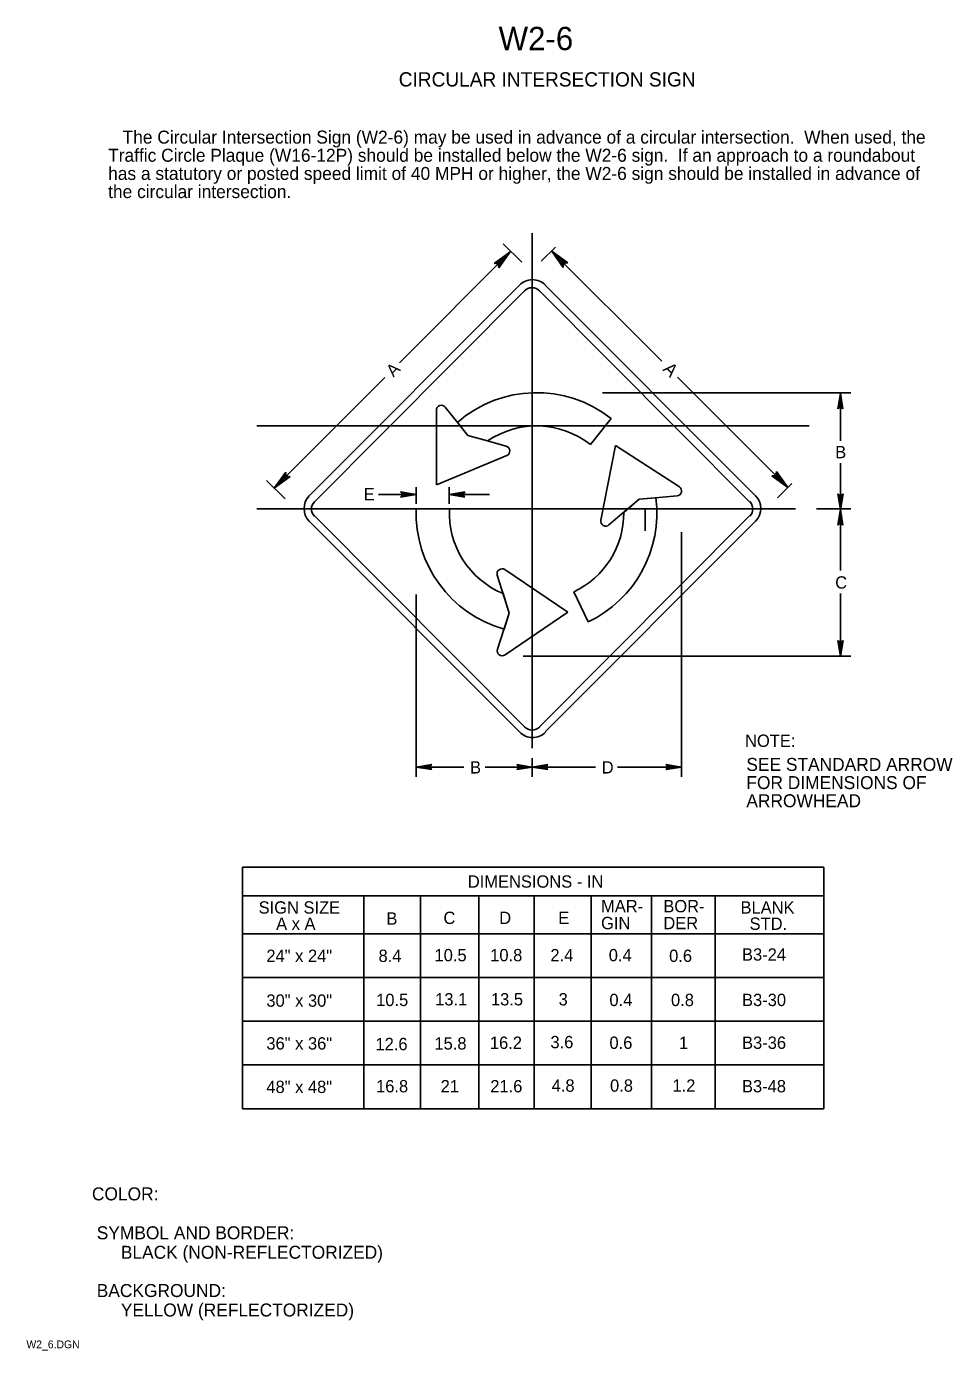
# Model space of a CAD drawing. Extents: x 0.013 to 0.191, y 0.004 to 0.259.
import ezdxf

# ---------------------------------------------------------------- set-up
doc = ezdxf.new("R2010")
doc.units = 0
for name, color, linetype in [('1', 7, 'Continuous'), ('2', 7, 'Continuous'), ('3', 7, 'Continuous')]:
    doc.layers.add(name, color=color, linetype=linetype)

# ---------------------------------------------------------------- blocks, each defined once
blk = doc.blocks.new('RARROW')
at = {"layer": '3'}
for p, q in [((-2.156, 0.28500000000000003), (-2.2665, 0.384625)), ((-2.2665, 0.384625), (0, 0)), ((0, 0), (-2.2665, -0.379125)), ((-2.156, 0.28500000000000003), (-2.075625, 0.12075)), ((0, 0), (-2.156, 0.28500000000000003)), ((-2.14975, -0.2705), (0, 0)), ((-2.075625, 0.12075), (0, 0)), ((0, 0), (-2.074, -0.108)), ((-2.2665, -0.379125), (-2.14975, -0.2705)), ((-2.074, -0.108), (-2.14975, -0.2705))]:
    blk.add_line(p, q, dxfattribs=at)

msp = doc.modelspace()

# ---------------------------------------------------------------- linework, layer by layer
at = {"layer": '2'}
for p, q in [((0.09568552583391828, 0.18279025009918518), (0.09769312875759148, 0.1802751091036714)), ((0.0957700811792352, 0.18268431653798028), (0.09769312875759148, 0.1802751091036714)), ((0.12133620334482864, 0.17850114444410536), (0.12529810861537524, 0.18352740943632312)), ((0.09769312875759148, 0.1802751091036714), (0.10149251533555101, 0.17920169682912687)), ((0.09769312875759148, 0.1802751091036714), (0.10081141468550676, 0.1793941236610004)), ((0.08775000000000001, 0.17030520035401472), (0.08775000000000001, 0.1671072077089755)), ((0.094125, 0.17030520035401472), (0.094125, 0.1671072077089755)), ((0.09415526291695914, 0.1661072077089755), (0.08775000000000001, 0.1661072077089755)), ((0.13074093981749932, 0.16800281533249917), (0.12773569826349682, 0.1654377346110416)), ((0.13394559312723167, 0.1682750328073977), (0.13074093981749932, 0.16800281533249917)), ((0.13381247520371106, 0.16826372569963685), (0.13074093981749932, 0.16800281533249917)), ((0.138875, 0.1616072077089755), (0.138875, 0.11448220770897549)), ((0.08775000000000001, 0.1496072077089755), (0.08775000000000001, 0.11448220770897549)), ((0.10447937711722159, 0.14979755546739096), (0.105681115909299, 0.14600468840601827)), ((0.105681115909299, 0.14600468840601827), (0.10470659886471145, 0.14909501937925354)), ((0.11813620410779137, 0.15012827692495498), (0.12087905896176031, 0.14434582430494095)), ((0.105681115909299, 0.14600468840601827), (0.10469034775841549, 0.14296376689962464)), ((0.10472218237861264, 0.1430750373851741), (0.105681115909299, 0.14600468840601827)), ((0.08775000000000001, 0.116375), (0.09693749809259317, 0.116375)), ((0.10106250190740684, 0.116375), (0.110125, 0.116375)), ((0.110125, 0.116375), (0.12231250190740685, 0.116375)), ((0.12656250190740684, 0.116375), (0.138875, 0.116375))]:
    msp.add_line(p, q, dxfattribs=at)
for radius, start, end in [(0.023200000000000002, 51.75337929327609, 131.0986026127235), (0.016800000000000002, 51.75338012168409, 124.20282927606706), (0.023200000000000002, 178.02389171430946, 254.38226787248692), (0.016800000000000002, 177.2705973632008, 247.39753928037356), (0.023200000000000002, 295.3769334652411, 7.349614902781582), (0.016800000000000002, 295.37693352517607, 0.4451615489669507)]:
    msp.add_arc((0.11093620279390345, 0.1653072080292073), radius, start, end, dxfattribs=at)
at = {"layer": '3'}
for p, q in [((0.10809834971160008, 0.21363385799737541), (0.1045232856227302, 0.21720892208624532)), ((0.110125, 0.2192322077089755), (0.110125, 0.1199822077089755)), ((0.08451462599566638, 0.19426462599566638), (0.10599110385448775, 0.21574110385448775)), ((0.1118516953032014, 0.21383413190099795), (0.11458199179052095, 0.21656442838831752)), ((0.1350682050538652, 0.19455679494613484), (0.11382128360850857, 0.21580371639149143)), ((0.067125, 0.168625), (0.107625, 0.20925)), ((0.112625, 0.20925), (0.153125, 0.168625)), ((0.068125, 0.1675), (0.108625, 0.208125)), ((0.1115, 0.208125), (0.152, 0.1675)), ((0.060375, 0.170125), (0.08166862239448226, 0.19141862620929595)), ((0.13809929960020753, 0.19152570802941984), (0.15937500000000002, 0.17025)), ((0.123625, 0.1885), (0.1715, 0.1885)), ((0.1695, 0.1792322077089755), (0.1695, 0.1884822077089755)), ((0.09168351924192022, 0.17072331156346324), (0.09163820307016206, 0.18511620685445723)), ((0.09334848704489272, 0.18571811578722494), (0.0957700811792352, 0.18268431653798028)), ((0.057, 0.182125), (0.1635, 0.182125)), ((0.0957700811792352, 0.18268431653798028), (0.09769312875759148, 0.1802751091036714)), ((0.09769312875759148, 0.1802751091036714), (0.10081141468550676, 0.1793941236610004)), ((0.10081141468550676, 0.1793941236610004), (0.10508310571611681, 0.17818727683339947)), ((0.10519276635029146, 0.1763778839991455), (0.09168351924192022, 0.17072331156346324)), ((0.1233345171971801, 0.16393122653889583), (0.12613620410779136, 0.1783056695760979)), ((0.12613620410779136, 0.1783056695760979), (0.13846514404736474, 0.17038604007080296)), ((0.1695, 0.1661072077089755), (0.1695, 0.1749175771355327)), ((0.0624779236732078, 0.16803030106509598), (0.05890296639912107, 0.17160525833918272)), ((0.15740165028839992, 0.16825885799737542), (0.16014460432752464, 0.17100181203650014)), ((0.0805, 0.168875), (0.08775000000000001, 0.168875)), ((0.094125, 0.168875), (0.10187845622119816, 0.168875)), ((0.13802755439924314, 0.16862176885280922), (0.13381247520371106, 0.16826372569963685)), ((0.057, 0.1661072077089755), (0.160875, 0.1661072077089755)), ((0.12827629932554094, 0.16589915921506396), (0.12490002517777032, 0.16301738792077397)), ((0.13074093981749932, 0.16800281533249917), (0.12827629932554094, 0.16589915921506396)), ((0.13381247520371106, 0.16826372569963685), (0.13074093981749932, 0.16800281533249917)), ((0.131875, 0.166125), (0.131875, 0.161875)), ((0.131875, 0.166125), (0.131875, 0.163625)), ((0.131875, 0.166125), (0.131875, 0.163625)), ((0.1715, 0.1661072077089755), (0.164875, 0.1661072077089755)), ((0.1695, 0.1542322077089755), (0.1695, 0.1661072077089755)), ((0.107625, 0.123125), (0.067125, 0.16375)), ((0.108625, 0.124125), (0.068125, 0.16475)), ((0.152, 0.16475), (0.1115, 0.124125)), ((0.153125, 0.16375), (0.112625, 0.123125)), ((0.10470659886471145, 0.14909501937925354), (0.10337162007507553, 0.15332841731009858)), ((0.10482412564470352, 0.1544129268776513), (0.11696407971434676, 0.14622173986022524)), ((0.105681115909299, 0.14600468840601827), (0.10470659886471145, 0.14909501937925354)), ((0.1695, 0.13775), (0.1695, 0.149832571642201)), ((0.10472218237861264, 0.1430750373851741), (0.105681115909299, 0.14600468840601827)), ((0.11696407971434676, 0.14622173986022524), (0.10485965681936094, 0.13796302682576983)), ((0.103406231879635, 0.13905466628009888), (0.10472218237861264, 0.1430750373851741)), ((0.110125, 0.14300000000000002), (0.110125, 0.144875)), ((0.108375, 0.13775), (0.1715, 0.13775)), ((0.110125, 0.1181072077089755), (0.110125, 0.11448220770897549)), ((0.054294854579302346, 0.09709144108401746), (0.16627504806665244, 0.09709144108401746)), ((0.054294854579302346, 0.09709144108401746), (0.054294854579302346, 0.05052360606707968)), ((0.16627504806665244, 0.09709144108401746), (0.16627504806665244, 0.05052360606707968)), ((0.16627504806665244, 0.09152782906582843), (0.054294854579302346, 0.09152782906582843)), ((0.07764135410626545, 0.09152782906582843), (0.07764135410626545, 0.05052360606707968)), ((0.08859135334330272, 0.09152782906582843), (0.08859135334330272, 0.05052360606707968)), ((0.09979911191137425, 0.09152782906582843), (0.09979911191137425, 0.05052360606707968)), ((0.11049135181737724, 0.09152782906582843), (0.11049135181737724, 0.05052360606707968)), ((0.1214552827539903, 0.09152782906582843), (0.1214552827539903, 0.05052360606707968)), ((0.13307547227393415, 0.09152782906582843), (0.13307547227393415, 0.05052360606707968)), ((0.1453588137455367, 0.09152782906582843), (0.1453588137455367, 0.05052360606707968)), ((0.054294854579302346, 0.08426226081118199), (0.16627504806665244, 0.08426226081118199)), ((0.054294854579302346, 0.07582759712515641), (0.16627504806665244, 0.07582759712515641)), ((0.054294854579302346, 0.06739293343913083), (0.16627504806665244, 0.06739293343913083)), ((0.054294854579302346, 0.05895826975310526), (0.16627504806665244, 0.05895826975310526)), ((0.054294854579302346, 0.05052360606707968), (0.16627504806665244, 0.05052360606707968))]:
    msp.add_line(p, q, dxfattribs=at)
for centre, radius, start, end in [((0.11014096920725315, 0.20674707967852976), 0.003536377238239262, 44.423908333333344, 135.3533277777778), ((0.11007125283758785, 0.20670173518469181), 0.0020166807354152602, 44.88986111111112, 135.81928055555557), ((0.09259819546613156, 0.18511922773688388), 0.00096, 38.59706823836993, 180.18039620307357), ((0.10482209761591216, 0.1772634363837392), 0.0009600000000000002, 292.7127526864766, 74.22383721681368), ((0.06959537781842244, 0.16616970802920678), 0.003470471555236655, 135.38381666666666, 224.61618055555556), ((0.13794630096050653, 0.16957832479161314), 0.0009600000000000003, 274.85525458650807, 57.28489031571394), ((0.1506301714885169, 0.16615999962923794), 0.003517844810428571, 316.1381361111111, 45.12422222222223), ((0.0695185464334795, 0.16610720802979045), 0.0019577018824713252, 135.38381666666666, 224.61618055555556), ((0.15060956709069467, 0.1661123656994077), 0.0019956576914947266, 315.85381666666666, 44.83990277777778), ((0.1242767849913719, 0.1637475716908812), 0.00096, 168.97089764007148, 310.4819776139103), ((0.10428717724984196, 0.15361713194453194), 0.00096, 55.99129694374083, 197.50237691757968), ((0.1043185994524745, 0.13875602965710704), 0.0009600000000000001, 161.87565389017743, 304.3052896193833), ((0.11018066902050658, 0.12552070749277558), 0.0034716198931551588, 223.19229722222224, 315.73071111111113), ((0.11010323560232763, 0.12550403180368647), 0.002011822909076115, 223.10040555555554, 315.63881944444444)]:
    msp.add_arc(centre, radius, start, end, dxfattribs=at)

# ---------------------------------------------------------------- block references
for p, xscale, yscale, rotation in [((0.105875, 0.215625), 0.0016545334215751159, 0.0016366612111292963, 44.999999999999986), ((0.113875, 0.21575), 0.0016545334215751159, 0.0016366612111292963, 135.00000000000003), ((0.1695, 0.18837500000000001), 0.0013236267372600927, 0.001309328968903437, 90), ((0.060375, 0.170125), 0.001654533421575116, 0.001636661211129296, -135), ((0.15937500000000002, 0.17025), 0.0016545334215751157, 0.001636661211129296, -45), ((0.094125, 0.168875), 0.0013236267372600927, 0.001309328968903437, 180), ((0.1695, 0.166), 0.0013236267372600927, 0.001309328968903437, -90), ((0.1695, 0.166), 0.0013236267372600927, 0.001309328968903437, 90), ((0.1695, 0.13775), 0.0013236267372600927, 0.001309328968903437, -90), ((0.08775000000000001, 0.116375), 0.0013236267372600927, 0.001309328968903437, 180), ((0.110125, 0.116375), 0.0013236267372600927, 0.001309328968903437, 180)]:
    msp.add_blockref('RARROW', p, dxfattribs=dict(at, xscale=xscale, yscale=yscale, rotation=rotation))
at = {"layer": '3', "xscale": 0.0013236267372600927, "yscale": 0.001309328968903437}
for p in [(0.08775000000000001, 0.168875), (0.110125, 0.116375), (0.138875, 0.116375)]:
    msp.add_blockref('RARROW', p, dxfattribs=at)

# ---------------------------------------------------------------- texts
at = {"layer": '1'}
for s, height, p in [('W2-6', 0.0045000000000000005, (0.10362500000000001, 0.2545)), ('CIRCULAR INTERSECTION SIGN', 0.00275025, (0.084375, 0.2475)), ('NOTE:', 0.0023752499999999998, (0.151125, 0.12025)), ('SEE STANDARD ARROW', 0.0024997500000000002, (0.151375, 0.115625)), ('FOR DIMENSIONS OF', 0.0024997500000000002, (0.151375, 0.112125)), ('ARROWHEAD', 0.0024997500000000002, (0.151375, 0.108625)), ('COLOR:', 0.0024997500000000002, (0.02525, 0.032875)), (' SYMBOL AND BORDER:', 0.0024997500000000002, (0.02525, 0.025375)), ('      BLACK (NON-REFLECTORIZED)', 0.0024997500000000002, (0.02525, 0.021625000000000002)), (' BACKGROUND:', 0.0024997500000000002, (0.02525, 0.01425)), ('      YELLOW (REFLECTORIZED)', 0.0024997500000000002, (0.02525, 0.0105)), ('W2_6.DGN', 0.0015, (0.012625, 0.004375))]:
    msp.add_text(s, height=height, dxfattribs=at).set_placement(p)
at = {"layer": '2'}
for s, height, p in [('   The Circular Intersection Sign (W2-6) may be used in advance of a circular intersection.  When used, the', 0.0024997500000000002, (0.028375, 0.23650025)), ('Traffic Circle Plaque (W16-12P) should be installed below the W2-6 sign.  If an approach to a roundabout ', 0.0024997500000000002, (0.028375, 0.2330005)), ('has a statutory or posted speed limit of 40 MPH or higher, the W2-6 sign should be installed in advance of ', 0.0024997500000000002, (0.028375, 0.22950075)), ('the circular intersection.', 0.0024997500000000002, (0.028375, 0.226001)), ('B', 0.0023752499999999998, (0.098125, 0.115125)), ('D', 0.0023752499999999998, (0.1235, 0.115125))]:
    msp.add_text(s, height=height, dxfattribs=at).set_placement(p)
msp.add_text('A', height=0.0023752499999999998, rotation=45.00000555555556, dxfattribs=at).set_placement((0.083375, 0.19137500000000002))
at = {"layer": '3'}
msp.add_text('A', height=0.0024997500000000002, rotation=315, dxfattribs=at).set_placement((0.135125, 0.192875))
for s, p in [('B', (0.1685, 0.175875)), ('E', (0.077625, 0.16775)), ('C', (0.1685, 0.15075)), ('DIMENSIONS - IN', (0.09769159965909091, 0.093125)), ('SIGN SIZE', (0.057375, 0.088125)), ('MAR-', (0.123375, 0.088375)), ('BOR-', (0.135375, 0.088375)), ('BLANK', (0.15025, 0.088125)), ('A x A', (0.06075, 0.085)), ('B', (0.082, 0.08600000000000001)), ('C', (0.093, 0.08612500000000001)), ('D', (0.10375000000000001, 0.08612500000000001)), ('E', (0.115125, 0.08612500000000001)), ('GIN', (0.123375, 0.085125)), ('DER', (0.135375, 0.085125)), ('STD.', (0.152, 0.085)), ('24" x 24"', (0.058870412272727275, 0.078812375)), ('8.4', (0.08048199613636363, 0.078812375)), ('10.5', (0.09127661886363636, 0.078937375)), ('10.8', (0.10201078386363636, 0.078937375)), ('2.4', (0.11360699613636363, 0.078937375)), ('0.4', (0.12485699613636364, 0.078937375)), ('0.6', (0.13649351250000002, 0.078812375)), ('B3-24', (0.1505371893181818, 0.079062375)), ('30" x 30"', (0.058870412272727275, 0.07018737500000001)), ('10.5', (0.08002661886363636, 0.07031237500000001)), ('13.1', (0.09139562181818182, 0.07043737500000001)), ('13.5', (0.10215161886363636, 0.07043737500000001)), ('3', (0.11518161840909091, 0.07043737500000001)), ('0.4', (0.12498199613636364, 0.07031237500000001)), ('0.8', (0.1368555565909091, 0.07031237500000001)), ('B3-30', (0.15054366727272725, 0.07031237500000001)), ('36" x 36"', (0.058870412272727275, 0.061937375)), ('12.6', (0.07989873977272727, 0.061812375)), ('15.8', (0.09126078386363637, 0.061937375)), ('16.2', (0.10195020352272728, 0.062062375)), ('3.6', (0.11361851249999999, 0.062187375)), ('0.6', (0.1249935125, 0.062062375)), ('1', (0.13839395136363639, 0.062062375)), ('B3-36', (0.1505487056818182, 0.062062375)), ('4.8', (0.1138555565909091, 0.053812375)), ('0.8', (0.12510555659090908, 0.053812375)), ('1.2', (0.13713590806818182, 0.053812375)), ('48" x 48"', (0.058870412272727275, 0.053562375)), ('16.8', (0.08001078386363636, 0.053687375)), ('21', (0.09245824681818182, 0.053687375)), ('21.6', (0.10202373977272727, 0.053687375)), ('B3-48', (0.15053574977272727, 0.053687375))]:
    msp.add_text(s, height=0.0023752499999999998, dxfattribs=at).set_placement(p)

doc.saveas('drawing.dxf')
